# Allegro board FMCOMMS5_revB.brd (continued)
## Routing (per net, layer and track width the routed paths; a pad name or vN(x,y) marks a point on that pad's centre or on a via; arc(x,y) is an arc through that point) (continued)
TX_D5_N_B: length 84.6
  TOP w0.203: P402.H20 v1(78.73,33.28)
  L6_SIG w0.097: v2(26.63,26.71) 26.4,26.95 26.4,27.41 26.15,27.66 26.15,28.03 26.4,28.27 26.4,28.55 26.16,28.78 26.16,29.17 26.4,29.4 26.4,29.68 26.12,29.96 26.12,30.21 26.4,30.49 26.4,30.81 26.09,31.11 26.09,31.37 26.4,31.68 26.4,38.81 30.01,42.41 46.15,42.41 46.28,42.29 46.28,40.48 46.55,40.2 48.67,40.2 48.95,40.48 48.95,42.42 49.08,42.55 50.2,42.55 50.33,42.42 50.33,38.56 50.61,38.28 52.18,38.28 52.46,38.56 52.46,40.3 52.68,40.52 72.97,40.52 73.17,40.32 73.17,38.83 77.57,34.43 79.1,34.43 79.53,34 79.53,33.17 79.4,33.04 78.87,33.04 78.73,33.18 v1(78.73,33.28)
  BOTTOM w0.203: U201.F8 v2(26.63,26.71)
TX_D5_P_A: length 84.5
  TOP w0.203: P401.H19 v1(80,103.24)
  L6_SIG w0.097: v1(80,103.24) 79.77,103.47 79.77,104.06 79.19,104.64 74.77,104.64 74.23,105.18 74.23,107.98 73.8,108.42 72.47,108.42 72.35,108.54 72.35,110.36 72.07,110.64 70.34,110.64 70.06,110.36 70.06,108.55 69.86,108.34 68.05,108.34 67.96,108.44 67.96,110.42 67.71,110.66 65.56,110.66 65.32,110.42 65.32,108.44 65.22,108.34 63.29,108.34 63.19,108.44 63.19,110.42 62.95,110.66 60.8,110.66 60.55,110.42 60.55,108.44 60.46,108.34 58.52,108.34 58.43,108.44 58.43,110.42 58.18,110.66 56.03,110.66 55.79,110.42 55.79,108.44 55.69,108.34 53.76,108.34 53.66,108.44 53.66,110.32 53.38,110.6 51.3,110.6 51.02,110.32 51.02,108.44 50.93,108.34 48.99,108.34 48.9,108.44 48.9,110.42 48.65,110.66 44.27,110.66 42.65,112.28 31.56,112.28 31.16,112.69 30.65,112.69 30.55,112.59 30.3,112.59 30.2,112.69 29.73,112.69 29.64,112.6 29.16,112.6 29.07,112.69 28.59,112.69 28.5,112.6 28.03,112.6 27.94,112.69 27.46,112.69 27.37,112.6 26.9,112.6 26.81,112.69 26.33,112.69 26,112.36 v2(25.34,112.36)
  BOTTOM w0.203: U101.E7 v2(25.34,112.36)
TX_D5_P_B: length 84.6
  TOP w0.203: P402.H19 v1(80,33.28)
  L6_SIG w0.097: v2(26.07,26.15) 26.07,26.81 25.74,27.14 25.74,27.62 25.83,27.71 25.83,28.18 25.74,28.27 25.74,28.75 25.83,28.84 25.83,29.32 25.74,29.4 25.74,29.88 25.83,29.97 25.83,30.45 25.74,30.54 25.74,31.01 25.84,31.11 25.84,31.37 25.74,31.46 25.74,31.97 26.15,32.38 26.15,38.91 29.9,42.67 46.26,42.67 46.53,42.39 46.53,40.58 46.66,40.46 48.57,40.46 48.69,40.58 48.69,42.53 48.97,42.8 50.31,42.8 50.58,42.53 50.58,38.66 50.71,38.53 52.08,38.53 52.2,38.66 52.2,40.4 52.58,40.77 73.08,40.77 73.42,40.43 73.42,38.94 77.67,34.68 79.2,34.68 79.78,34.1 79.78,33.5 v1(80,33.28)
  BOTTOM w0.203: U201.E7 v2(26.07,26.15)
TX_EXT_LO_A: length 47.3
  TOP w0.394: C337.2 34.41,73.8 arc(34.41,74) 34.39,74.19 arc(34.11,75.11) 33.55,75.9 29.71,79.74 18.49,90.96 arc(17.41,92.48) 16.91,94.28 16.91,100.35 arc(17.13,101.49) 17.78,102.45 arc(18.3,102.8) 18.92,102.93 22.57,102.93 arc(23.76,103.16) 24.76,103.83 25.53,104.61 arc(25.76,104.95) v3(25.84,105.35)
  BOTTOM w0.254: v3(25.84,105.35) 25.84,105.5 25.34,106 U101.A12
TX_EXT_LO_B: length 47.2
  TOP w0.394: C339.2 34.59,66.15 arc(34.37,65.02) 33.72,64.05 29.89,60.22 arc(28.3,57.85) 27.75,55.05 27.75,43.51 arc(28.2,41.21) 29.51,39.26 32.02,36.75 arc(33.76,34.13) 34.38,31.05 34.38,30.06 arc(34.12,28.78) 33.4,27.7 31.15,25.44 v2(31.15,25.44)
  BOTTOM w0.254: v2(31.15,25.44) 31.16,25.45 U201.A12
TX_FRAME_N_A: length 84.5
  TOP w0.203: P401.D15 v1(83.81,96.89)
  L6_SIG w0.097: v2(28.16,112.93) 28.4,113.17 28.87,113.17 29.16,113.46 29.43,113.46 29.72,113.17 30,113.17 30.28,113.44 30.58,113.44 30.86,113.17 31.13,113.17 31.44,113.48 31.68,113.48 31.71,113.45 31.99,113.17 32.26,113.17 32.66,113.57 36.54,113.57 37.26,112.85 42.81,112.85 43.87,111.8 46.18,111.8 46.46,112.07 46.46,113.02 46.58,113.14 48.46,113.14 48.59,113.02 48.59,111.62 48.86,111.34 50.95,111.34 51.22,111.62 51.22,112.97 51.35,113.09 53.22,113.09 53.35,112.97 53.35,111.28 53.63,111.01 55.71,111.01 55.99,111.28 55.99,112.66 56.11,112.79 57.99,112.79 58.12,112.66 58.12,111.38 58.39,111.1 60.48,111.1 60.75,111.38 60.75,112.7 60.88,112.83 62.75,112.83 62.88,112.7 62.88,111.5 63.16,111.23 72.79,111.23 75.5,108.52 75.5,105.93 75.77,105.65 79.86,105.65 80.32,105.19 80.32,103.77 80.96,103.14 84.21,103.14 84.6,102.75 84.6,96.72 84.46,96.59 83.95,96.59 83.81,96.73 v1(83.81,96.89)
  BOTTOM w0.203: U101.H9 v2(28.16,112.93)
TX_FRAME_N_B: length 86.2
  TOP w0.203: P402.D15 v1(83.81,26.93)
  L6_SIG w0.097: v2(25.5,28.97) 25.28,28.97 25.14,29.12 25.14,29.26 25.27,29.39 25.27,29.68 24.97,29.98 24.97,30.24 25.27,30.54 25.27,30.81 24.99,31.09 24.99,31.39 25.27,31.67 25.27,31.94 24.95,32.25 24.95,32.63 24.86,32.72 24.86,36.57 25.76,37.46 25.76,39.53 29.59,43.35 36.65,43.35 36.74,43.44 50.55,43.44 52.42,41.58 72.86,41.58 77.42,37.02 78.5,37.02 81.12,34.4 83.66,34.4 84.61,33.45 84.61,26.56 84.48,26.43 83.94,26.43 83.81,26.56 v1(83.81,26.93)
  BOTTOM w0.203: U201.H9 v2(25.5,28.97)
TX_FRAME_P_A: length 84.5
  TOP w0.203: P401.D14 v1(85.08,96.89)
  L6_SIG w0.097: v1(85.08,96.89) 84.85,97.11 84.85,102.85 84.31,103.39 81.06,103.39 80.58,103.88 80.58,105.3 79.97,105.91 75.88,105.91 75.75,106.03 75.75,108.63 72.9,111.48 63.26,111.48 63.13,111.61 63.13,112.81 62.86,113.08 60.77,113.08 60.5,112.81 60.5,111.49 60.37,111.36 58.5,111.36 58.37,111.49 58.37,112.77 58.09,113.04 56.01,113.04 55.73,112.77 55.73,111.39 55.61,111.26 53.73,111.26 53.6,111.39 53.6,113.07 53.33,113.35 51.24,113.35 50.97,113.07 50.97,111.72 50.84,111.59 48.97,111.59 48.84,111.72 48.84,113.12 48.56,113.4 46.48,113.4 46.2,113.12 46.2,112.18 46.08,112.05 43.97,112.05 42.92,113.1 37.36,113.1 36.65,113.82 31.78,113.82 31.69,113.73 31.42,113.73 31.33,113.82 30.52,113.82 30.43,113.74 30.08,113.74 30,113.82 29.52,113.82 29.43,113.73 28.95,113.73 28.87,113.82 28.52,113.82 27.63,112.93 v2(27.03,112.93)
  BOTTOM w0.203: U101.G9 v2(27.03,112.93)
TX_FRAME_P_B: length 86.2
  TOP w0.203: P402.D14 v1(85.08,26.93)
  L6_SIG w0.097: v2(25.5,27.84) 25.5,28.32 24.61,29.21 24.61,29.68 24.7,29.77 24.7,30.24 24.61,30.33 24.61,30.81 24.7,30.89 24.7,31.24 24.61,31.33 24.61,32.14 24.7,32.23 24.7,32.51 24.61,32.59 24.61,36.67 25.51,37.57 25.51,39.63 29.41,43.53 29.41,43.53 29.48,43.61 36.54,43.61 36.63,43.7 50.66,43.7 52.53,41.83 72.97,41.83 77.53,37.27 78.61,37.27 81.23,34.65 83.77,34.65 84.87,33.56 84.87,27.15 v1(85.08,26.93)
  BOTTOM w0.203: U201.G9 v2(25.5,27.84)
TX_MON1_A: length 36.4
  TOP w0.394: C101.2 41.45,128.66 arc(39.94,128.35) 38.65,127.49 35.75,124.6 arc(35.32,124.26) 34.83,124.04 arc(33.63,123.5) 32.59,122.69 28.53,118.63 arc(28.25,118.2) 28.14,117.7 v2(28.14,117.6)
  BOTTOM w0.254: v2(28.14,117.6) U101.M5
TX_MON1_B: length 27.2
  TOP w0.394: C201.2 8.17,21.6 arc(9.02,25.86) 11.44,29.48 13.16,31.2 arc(15.54,32.19) 17.91,31.2 19.69,29.43 arc(20.21,29.08) v2(20.83,28.96)
  BOTTOM w0.254: v2(20.83,28.96) U201.M5
TX_MON2_A: length 20.8
  TOP w0.394: C102.2 8.21,119.03 arc(10.62,113.23) 16.42,110.83 v2(20.98,110.83)
  BOTTOM w0.254: v2(20.98,110.83) U101.A5
TX_MON2_B: length 36.8
  TOP w0.394: C202.2 44.23,13.04 arc(36.32,14.75) 29.82,19.57 v2(27.6,21.79)
  BOTTOM w0.254: v2(27.6,21.79) U201.A5
TX_VCO_1P1V_SUPPLY_A: length 3.9
  TOP w0.394: C104.2 24.93,106.46 24.93,106.95 R123.1 25.34,107.36 v2(25.34,107.84) v2(25.9,108.4)
  BOTTOM w0.254: v2(25.34,107.84) U101.A11 ; U101.B11 v2(25.9,108.4)
TX_VCO_1P1V_SUPPLY_B: length 4.6
  TOP w0.305: v2(30.03,26.71) v2(30.59,26.15) 30.73,26.28 30.73,26.89 31.21,27.37 C204.2 R223.1
  BOTTOM w0.254: v2(30.59,26.15) U201.A11 ; v2(30.03,26.71) U201.B11
TXNRX_A: length 90.5
  TOP w0.394: 80.63,102.6 v1(81.8,102.6)
  L5_SIG w0.124: v1(81.8,102.6) 82.2,102.6 82.33,102.73 82.33,103.03 82.45,103.16 83.87,103.16 83.99,103.29 83.99,103.72 84.12,103.84 84.88,103.84 85.01,103.72 85.01,102.91 85.13,102.78 86.01,102.78 86.14,102.66 86.14,102.02 86.01,101.9 84.78,101.9 84.65,101.77 84.65,101.14 84.78,101.01 86.14,101.01 86.27,100.88 86.27,100.25 86.14,100.12 85.07,100.12 85.07,100.12 83.96,100.12 83.84,100.25 83.84,101.77 83.71,101.89 80.73,101.89 80.6,102.02 80.6,102.52 80.47,102.64 79.33,102.64 79.2,102.77 79.2,103.81 78.91,104.1 77.55,104.1 77.13,104.53 77.13,107.54 77.01,107.67 74.5,107.67 74.37,107.8 74.37,109.4 74.24,109.52 52.72,109.52 47.25,115 45.12,115 44.05,116.07 44.05,117.87 P101.2 41.84,120.09 38.72,120.09 38.57,119.94 29.19,119.94 29.12,120.01 27.98,120.01 24.99,117.03 24.99,116.55 v2(24.77,116.32)
  BOTTOM w0.254: U101.H4 v2(24.77,116.32)
TXNRX_B: length 89.4
  TOP w0.394: 80.63,32.65 v1(81.8,32.65)
  L5_SIG w0.124: v2(22.11,25.58) 22.11,25.58 21.89,25.81 21.4,25.81 19.16,28.05 19.16,35.42 23.58,39.84 25.48,39.84 28.07,42.43 31.58,42.43 34.45,45.3 38.06,45.3 42.03,49.27 P201.2 44.28,47.95 44.28,46.1 50.68,39.7 74.17,39.7 78.07,35.79 78.33,35.79 81.48,32.65 v1(81.8,32.65)
  BOTTOM w0.254: U201.H4 v2(22.11,25.58)
UNNAMED_2_AD9361_I22_RBIAS: length 2.6
  BOTTOM w0.178: 26.47,118.02 27.19,118.74 27.19,118.86 R125.1
  BOTTOM w0.254: 26.47,118.02 U101.L4
UNNAMED_2_AD9361_I22_RXVCOLDOOU: length 3.6
  TOP w0.305: R124.1 22.4,116.92
  TOP w0.356: 22.4,116.92 22.51,116.81 v2(22.51,116.32)
  TOP w0.394: v2(22.51,116.32) v2(23.07,115.76)
  BOTTOM w0.254: U101.G3 v2(23.07,115.76) ; U101.G2 v2(22.51,116.32)
UNNAMED_2_AD9361_I22_XTALN: length 2.7
  BOTTOM w0.254: 31.56,113.49 31.66,113.49 32.31,112.84 C166.2 C165.2
UNNAMED_2_ADL5320_I366_RFIN: length 4.4
  BOTTOM w0.394: U104.1 47.27,125.59 C156.2 ; C156.2 45.51,125.58 FL102.2 44.23,125.59 C156.2
UNNAMED_2_ADL5320_I366_RFOUT: length 5.5
  BOTTOM w0.394: C139.2 53.34,125.96 53.35,125.96 L110.1 C155.2 U104.3
UNNAMED_2_ADL5320_I367_RFIN: length 3.1
  BOTTOM w0.394: FL103.2 11.3,96.75 C114.2 11.31,96.74 U105.1
UNNAMED_2_ADL5320_I367_RFOUT: length 5.5
  BOTTOM w0.394: U105.3 C115.2 L111.1 13.75,88.89 C162.2
UNNAMED_2_ADL5521PRELIM_I290__1: length 3.9
  BOTTOM w0.305: U102.7 15.83,127.27
  BOTTOM w0.394: FL100.4 17.53,125.75 arc(17.25,125.93) 16.92,126 arc(16.15,126.32) 15.83,127.09 15.83,127.27
UNNAMED_2_ADL5521PRELIM_I290_RF: length 1.5
  BOTTOM w0.305: 15.83,131.2 U102.2
  BOTTOM w0.394: 15.83,131.2 15.83,131.64 15.84,131.65 L106.2
UNNAMED_2_ADL5521PRELIM_I290_VB: length 3
  BOTTOM w0.305: 14.94,130.57 U102.1
  BOTTOM w0.394: 14.94,130.57 14.55,130.57 14.28,130.31 14.28,129.68 13.75,129.14 R108.1
UNNAMED_2_ADL5521PRELIM_I290_VP: length 5
  BOTTOM w0.305: U102.8 14.96,127.87
  BOTTOM w0.394: 14.96,127.87 R108.2 C147.2 R109.1
UNNAMED_2_ADL5521PRELIM_I304__1: length 4.5
  BOTTOM w0.305: 11.79,123.13 U103.7
  BOTTOM w0.394: 11.79,123.13 14.65,123.13 arc(14.9,123.08) 15.11,122.94 FL101.4
UNNAMED_2_ADL5521PRELIM_I304_RF: length 1.5
  BOTTOM w0.305: 7.81,123.14 7.82,123.13 U103.2
  BOTTOM w0.394: L108.2 7.81,123.14
UNNAMED_2_ADL5521PRELIM_I304_VB: length 3
  BOTTOM w0.305: 8.41,122.24 U103.1
  BOTTOM w0.394: R110.1 9.84,121.04 9.3,121.58 8.68,121.58 8.41,121.84 8.41,122.24
UNNAMED_2_ADL5521PRELIM_I304_VP: length 5
  BOTTOM w0.305: 11.11,122.24 U103.8
  BOTTOM w0.394: R112.1 C149.2 R110.2 11.11,122.24
UNNAMED_2_CAP_I19_N1: length 1.1
  TOP w0.394: R124.2 22.12,118.06 21.71,118.47 21.71,118.52 C117.1
UNNAMED_2_CAP_I51_N1: length 1.1
  TOP w0.394: R123.2 C105.1
UNNAMED_2_CAP_I135_N1: length 2.1
  BOTTOM w0.203: T106.6 30.08,124.08 28.99,124.08 C106.1
UNNAMED_2_CAP_I136_N1: length 2.1
  BOTTOM w0.203: C107.1 28.2,124.69 28.2,125.79 T106.4
UNNAMED_2_CAP_I137_N1: length 2.1
  BOTTOM w0.203: T105.6 13,110.59 14.09,110.59 C108.1
UNNAMED_2_CAP_I138_N1: length 2.1
  BOTTOM w0.203: T105.4 14.93,108.92 14.93,110.02 C109.1
UNNAMED_2_CAP_I199_N1: length 0.9
  TOP w0.394: C102.1 R122.2
UNNAMED_2_CAP_I200_N1: length 0.9
  TOP w0.394: C101.1 R121.2
UNNAMED_2_CAP_I209_N2: length 2.1
  BOTTOM w0.203: C122.2 33.63,119.98 34.72,119.98 T107.6
UNNAMED_2_CAP_I210_N2: length 2.1
  BOTTOM w0.203: T107.4 32.9,121.74 32.9,120.65 C123.2
UNNAMED_2_CAP_I220_N2: length 2.1
  BOTTOM w0.203: C124.2 18.18,105.88 17.08,105.88 T108.6
UNNAMED_2_CAP_I221_N2: length 2.1
  BOTTOM w0.203: T108.4 18.91,104.11 18.91,105.21 C125.2
UNNAMED_2_CAP_I230_N1: length 1.2
  BOTTOM w0.203: C128.1 21.79,120.9 arc(21.49,121.35) T101.3
UNNAMED_2_CAP_I231_N1: length 1.2
  BOTTOM w0.203: C129.1 21.11,120.21 arc(20.65,120.52) T101.4
UNNAMED_2_CAP_I232_N1: length 1.2
  BOTTOM w0.203: C130.1 19.18,118.28 arc(18.87,118.74) T102.3
UNNAMED_2_CAP_I233_N1: length 1.2
  BOTTOM w0.203: C131.1 18.5,117.6 arc(18.04,117.91) T102.4
UNNAMED_2_CAP_I260_N1: length 2
  TOP w0.203: C126.1 18.62,122.82 arc(18.44,123.74) T103.4
UNNAMED_2_CAP_I261_N1: length 2
  TOP w0.203: C127.1 17.82,122.02 arc(16.9,122.2) T103.6
UNNAMED_2_CAP_I271_N1: length 2.4
  BOTTOM w0.394: T108.3 14.98,100.19 arc(14.7,100) C140.1
UNNAMED_2_CAP_I271_N2: length 9.8
  BOTTOM w0.394: C111.1 C110.2
UNNAMED_2_CAP_I273_N1: length 8.2
  BOTTOM w0.394: T107.3 38.65,127.49 arc(39.94,128.35) 41.45,128.66 C136.1
UNNAMED_2_CAP_I273_N2: length 9.8
  BOTTOM w0.394: C137.1 C136.2
UNNAMED_2_CAP_I281_N2: length 2.1
  TOP w0.356: P101.16 60.45,119.25 C142.2
UNNAMED_2_CAP_I341_N2: length 2
  TOP w0.203: C132.2 34.74,119.73 arc(34.92,120.64) T104.6
UNNAMED_2_CAP_I342_N2: length 2
  TOP w0.203: C133.2 35.54,118.92 arc(36.46,119.11) T104.4
UNNAMED_2_CAP_I345_N2: length 2.5
  BOTTOM w0.394: C138.2 42.31,128.04 FL102.4
UNNAMED_2_CAP_I348_N2: length 2.5
  BOTTOM w0.394: FL103.4 13.75,99.94 C140.2
UNNAMED_2_CNBNC5P_I182_CNTR: length 16.5
  TOP w0.394: J101.1 71.12,133.35 arc(69.75,130.03) 66.43,128.66 R101.2 R121.1
UNNAMED_2_CNBNC5P_I183_CNTR: length 10.9
  TOP w0.394: R122.1 R102.2 8.21,128.43 arc(7.78,130.61) 6.55,132.45 J102.1
UNNAMED_2_FLTRBP4PV2_I360_OUT: length 1.5
  BOTTOM w0.394: T101.1 FL100.2
UNNAMED_2_FLTRBP4PV2_I361_OUT: length 1.5
  BOTTOM w0.394: T102.1 FL101.2
UNNAMED_3_CN160PCDGH_I39_N30: length 1.3
  TOP w0.394: 84.44,116.57 84.39,116.62 84.39,117.79 84.44,117.84
UNNAMED_3_CN160PCDGH_I54_N35: length 2.3
  TOP w0.508: 79.36,122.92 v1(78.2,122.92)
  BOTTOM w0.305: R404.1 78.19,122.93 v1(78.2,122.92)
UNNAMED_3_CN160PCDGH_I216_N30: length 1.3
  TOP w0.394: 84.44,47.89 84.44,46.62
UNNAMED_4_ADM7150_I1046_BYP: length 1.6
  TOP w0.394: U502.3 58.13,56.1 C538.2
UNNAMED_4_ADM7150_I1046_VIN: length 6.6
  TOP w0.394: 60.66,62.98 C535.2 C536.2
  TOP w0.508: 61.7,63 61.7,65.72 61.18,66.25 C644.2
UNNAMED_4_ADM7150_I1142_BYP: length 2.9
  TOP w0.394: U508.3 69.81,72 70.14,72.33 70.14,73.11 C643.2
UNNAMED_4_ADP237X_I1045_FB: length 3.9
  TOP w0.305: 67.33,63.48 U501.5
  TOP w0.394: 67.33,63.48 67.32,63.49 R502.1 R501.2
UNNAMED_4_ADP237X_I1045_SW: length 5.8
  TOP w0.305: U501.7 68.69,61.92
  TOP w0.394: 68.69,61.92 70.97,59.63 L502.1
UNNAMED_4_ADP1755_I730_ADJ: length 2.8
  TOP w0.394: R509.2 R508.1 49.18,82.08 49.47,81.8 U504.9
UNNAMED_4_ADP1755_I730_SS: length 1.5
  TOP w0.305: U504.7 C561.1
UNNAMED_4_ADP1755_I730_VOUT1: length 6
  TOP w0.305: 49.21,80.89 49.47,81.15 U504.10 ; 50.39,78.92 U504.13 U504.14 ; U504.12 49.25,79.85 ; U504.11 49.25,80.5
  TOP w0.394: C566.1 47.68,77.72 ; C565.1 45.85,77.72 ; C567.1 48.62,77.72 ; R508.2 48.62,81.03 ; C564.1 46.77,77.72
UNNAMED_4_ADP1755_I776_ADJ: length 2.8
  TOP w0.394: R513.2 R512.1 49.17,75.26 49.46,74.98 U505.9
UNNAMED_4_ADP1755_I776_SS: length 1.5
  TOP w0.305: U505.7 C577.1
UNNAMED_4_ADP1755_I776_VOUT1: length 5.9
  TOP w0.305: U505.11 49.24,73.68 ; U505.12 49.24,73.03 ; 49.2,74.07 49.46,74.33 U505.10 ; U505.14 U505.13 50.38,72.1
  TOP w0.394: C580.1 46.76,70.9 ; C582.1 47.67,70.9 ; R512.2 48.61,74.31 ; C583.1 45.84,70.9 ; C581.1 48.61,70.9
UNNAMED_4_ADP1755_I987_ADJ: length 2.8
  TOP w0.394: R517.2 R516.1 49.2,61.67 49.48,61.39 U506.9
UNNAMED_4_ADP1755_I987_SS: length 1.5
  TOP w0.305: C595.1 51.72,63.81 U506.7
UNNAMED_4_ADP1755_I987_VOUT1: length 5.9
  TOP w0.305: 49.22,60.48 49.48,60.74 U506.10 ; U506.11 49.26,60.09 ; U506.12 49.26,59.44 ; 50.41,58.51 U506.13 U506.14
  TOP w0.394: C598.1 48.64,57.31 ; R516.2 48.64,60.71 ; C514.1 46.78,57.31 ; C650.1 45.87,57.31 ; C599.1 47.7,57.31
UNNAMED_4_ADP1755_I997_ADJ: length 2.8
  TOP w0.394: R521.1 R520.1 49.21,68.48 49.5,68.19 U507.9
UNNAMED_4_ADP1755_I997_SS: length 1.5
  TOP w0.305: C621.1 51.72,69.93 51.74,69.91 U507.7
UNNAMED_4_ADP1755_I997_VOUT1: length 6
  TOP w0.305: U507.11 49.28,66.89 ; 49.24,67.28 49.5,67.54 U507.10 ; U507.12 49.28,66.24 ; U507.14 U507.13 50.42,65.32
  TOP w0.394: C626.1 46.8,64.11 ; C627.1 45.89,64.11 ; R520.2 48.65,67.4 ; C624.1 47.71,64.11 ; C625.1 48.65,64.11
UNNAMED_4_ADP2164_I831_FB: length 3
  TOP w0.305: U503.4 65.61,86.33 65.57,86.37
  TOP w0.394: R506.1 R505.2 65.34,86.6 65.57,86.37
UNNAMED_4_ADP2164_I831_PVIN1: length 9.4
  TOP w0.305: U503.13 70.4,82.55 v1(70.49,82.64)
  TOP w0.394: C505.1 71.03,83.55 ; R504.2 71.41,85.71 ; R523.2 71.03,84.52 ; C504.1 71.03,82.56 ; U503.12 68.84,81.55
  BOTTOM w0.394: E504.2 64.53,68 E503.1 64.51,70.17 64.51,71.29 ; 65.51,73.83 65.17,73.48 E501.1
  vias: v1(68.61,80.99) v1(69.4,80.99)
UNNAMED_4_ADP2164_I831_SW1: length 7.3
  TOP w0.305: 67.17,80.51 66.45,80.51 ; 67.17,80.51 67.34,80.51 67.66,80.19 L503.1 ; 67.17,80.51 66.91,80.76 U503.11 ; 66.45,80.51 66.26,80.7 U503.10 ; 66.45,80.51 65.9,80.51 65.61,80.79 U503.9
UNNAMED_4_ADP2164_I831_SYNC: length 4.6
  TOP w0.305: v3(68.54,85.38) 68.42,85.5 U503.1 ; U503.3 66.26,86.37 v3(66.25,86.37) ; U503.14 69.37,83.2 v3(69.4,83.17)
  TOP w0.394: v3(66.25,86.37) 66.45,86.57 C549.1 ; v3(72.85,84.85) 72.52,84.52 R523.1
UNNAMED_4_CAP_I833_N2: length 1.3
  TOP w0.394: C552.1 62.24,78.89 ; C551.1 63.43,78.76
UNNAMED_4_FERRITE_I816_N2: length 4.2
  BOTTOM w0.394: E514.1 E512.1 51.72,72.35 E515.2 E513.2 E1.1
UNNAMED_5_AD7291_I69_DCAP: length 1.8
  TOP w0.254: C313.1 40.33,47.75 40.09,47.51 U304.8
UNNAMED_5_AD7291_I69_VIN0: length 5
  TOP w0.305: U304.18 34.83,47.51 34.82,47.5 34.21,47.5 v3(34.1,47.62)
  L5_SIG w0.124: v3(35.06,49.44) 35.06,48.58 v3(34.1,47.62)
  BOTTOM w0.394: v3(35.06,49.44) 35.28,49.44 35.74,49.9 R305.2 35.74,50.94 R308.2
UNNAMED_5_AD7291_I69_VIN1: length 7.2
  TOP w0.254: U304.19 34.2,47.01 v3(34.07,46.88)
  BOTTOM w0.394: R307.2 R304.2 37.64,49.15 35.36,46.88 v3(34.07,46.88)
UNNAMED_5_AD7291_I69_VIN2: length 11.2
  TOP w0.305: v3(34.12,46.22) 34.15,46.22 34.44,46.51 U304.20
  BOTTOM w0.394: v3(34.12,46.22) 35.16,46.22 35.69,45.68 38.3,45.68 39.26,46.64 39.26,48.44 39.7,48.89 R303.2 R306.2
UNNAMED_5_AD7291_I69_VIN3: length 4.3
  TOP w0.254: U304.1 35.94,44.89 35.77,44.72 34.73,44.72 v3(34.2,44.18)
  BOTTOM w0.394: v3(34.2,44.18) R309.2 R312.2
UNNAMED_5_AD7291_I69_VIN4: length 3.3
  TOP w0.254: U304.2 36.44,44.58 v3(36.1,44.23)
  BOTTOM w0.394: v3(36.1,44.23) 36.31,44.03 R310.2 36.31,42.82 36.31,42.82 36.31,42.48 R313.2
UNNAMED_5_AD7291_I69_VIN5: length 3.3
  TOP w0.254: U304.3 36.94,44.25 v3(36.99,44.21)
  BOTTOM w0.394: R314.2 R327.2 37.51,43.69 v3(36.99,44.21)
UNNAMED_5_AD7291_I69_VIN6: length 4.2
  TOP w0.254: U304.4 37.44,44.64 37.93,44.16 v3(38.67,44.16)
  BOTTOM w0.394: R328.2 R326.2 39.28,43.55 v3(38.67,44.16)
UNNAMED_5_AD7291_I69_VIN7: length 6.6
  TOP w0.254: U304.5 37.94,44.91 38.23,44.62 39.15,44.62 39.71,44.06 41.64,44.06 v3(41.79,44.21)
  BOTTOM w0.394: v3(41.79,44.21) 41.66,44.08 R325.2 R329.2
UNNAMED_5_AD7291_I69_VREF: length 1.9
  TOP w0.254: U304.7 39.94,47.01 40.4,46.55 C314.1
UNNAMED_5_ADCLK846_I21_CLK: length 3.9
  TOP w0.305: 11.69,69.74 U301.3
  TOP w0.394: 11.69,69.74 11.45,69.5 10.04,69.5 ; C301.2 10.04,69.5 ; 10.04,69.5 R360.1
UNNAMED_5_ADCLK846_I21_CLKN: length 2.4
  TOP w0.305: U301.2 12.56,70.24 12.38,70.42
  TOP w0.394: C302.1 11.94,70.86 12.38,70.42
UNNAMED_5_ADCLK846_I21_OUT2: length 3
  TOP w0.203: U301.18 18.05,70.74 18.12,70.67 18.63,70.67 18.78,70.83 19.77,70.83 C318.1
UNNAMED_5_ADCLK846_I21_OUT2N: length 3
  TOP w0.203: U301.17 18.05,70.24 18.12,70.31 18.77,70.31 18.93,70.47 19.77,70.47 C319.1
UNNAMED_5_ADF5355_I6_CPOUT: length 4.6
  TOP w0.305: U302.7 26.45,67.32 26.63,67.15 C328.2
  TOP w0.394: R316.2 28.61,66.15 28.61,66.16 C329.2 C328.2
UNNAMED_5_ADF5355_I6_CREG1: length 2.1
  TOP w0.305: U302.25 22.21,72.4 21.95,72.66 21.67,72.66 21.3,73.03 C327.2
UNNAMED_5_ADF5355_I6_CREG2: length 2.4
  TOP w0.305: U302.32 22.25,68.9 21.5,68.16
  TOP w0.394: 21.5,68.16 21.31,67.97 C326.2
UNNAMED_5_ADF5355_I6_RFOUTB: length 4
  TOP w0.305: R335.2 29.94,72.32 29.01,71.4 U302.14
  TOP w0.394: R335.2 C353.2
UNNAMED_5_ADF5355_I6_RSET: length 2.5
  TOP w0.305: U302.22 24.45,73.6 25.48,74.64 R323.2
UNNAMED_5_ADF5355_I6_VBIAS: length 3.9
  TOP w0.305: U302.24 23.45,73.68 23.2,73.93 22.18,73.93 21.96,74.15 C322.2 21.96,75.8 C325.2
UNNAMED_5_ADF5355_I6_VREF: length 2.8
  TOP w0.305: C324.2 24.06,74.77 C321.2 24.07,74.03 23.95,73.92 U302.23
UNNAMED_5_ADF5355_I6_VTUNE: length 15.1
  TOP w0.305: U302.20 v3(25.45,73.9)
  TOP w0.394: v3(31.25,64.81) 31.18,64.88 C330.2 30.46,64.88 R316.1
  BOTTOM w0.394: v3(31.25,64.81) 31.18,64.88 30.93,64.88 27.64,68.16 27.64,72.4 26.15,73.9 v3(25.45,73.9)
UNNAMED_5_ADG91X_I150_RF1: length 1.6
  BOTTOM w0.305: C351.1 U306.8
UNNAMED_5_ADG91X_I150_RF2: length 1.6
  BOTTOM w0.305: U306.5 18.99,65.16 18.98,65.17 18.98,65.72 18.98,65.73 C352.1
UNNAMED_5_ADG91X_I150_RFC: length 27.2
  L6_SIG w0.124: v3(21.02,82.52) 22.83,80.71 22.83,66.27 21.81,65.25 20.55,65.25 18.71,63.41 18.71,61.11 v3(18.88,60.95)
  BOTTOM w0.305: v3(18.88,60.95) 18.99,60.84 U306.4 ; U305.4 21.01,82.51 v3(21.02,82.52)
UNNAMED_5_ADG91X_I151_RF1: length 1.8
  BOTTOM w0.305: U305.8 19.06,75 C349.2
UNNAMED_5_ADG91X_I151_RF2: length 1.8
  BOTTOM w0.305: U305.5 C350.2
UNNAMED_5_CAP_I5_N1: length 7.6
  TOP w0.394: C301.1 R301.2 J301.1
UNNAMED_5_CAP_I98_N1: length 1.6
  TOP w0.394: R315.2 27.21,64.17 27.62,64.58 C329.1
UNNAMED_5_CAP_I121_N1: length 1.5
  TOP w0.305: U307.2 35.13,72.56 35.3,72.72 C336.1
UNNAMED_5_CAP_I122_N1: length 1.5
  TOP w0.305: U307.3 34.63,72.5 34.41,72.72 C337.1
UNNAMED_5_CAP_I123_N1: length 1.9
  TOP w0.305: U307.11 35.13,67.77 35.13,67.76 35.13,67.55 35.47,67.21 C338.1
UNNAMED_5_CAP_I124_N1: length 1.7
  TOP w0.305: C339.1 34.59,67.73 34.63,67.76 U307.10
UNNAMED_5_CAP_I187_N2: length 13.7
  TOP w0.394: C390.2 31.88,72.32 C353.1 v1(31.89,73.01)
  L6_SIG w0.124: J302.1 32.4,79.92 32.4,73.57 31.89,73.07 v1(31.89,73.01)
UNNAMED_5_DIOLED_I51_P: length 1.5
  BOTTOM w0.394: R302.1 DS301.A
UNNAMED_5_RES_I192_N2: length 1.8
  TOP w0.394: Y301.3 10.62,71.16 arc(10.59,70.97) 10.49,70.79 10.05,70.35 R360.2
UNNAMED_9_AD9361_I119_RBIAS: length 2.6
  BOTTOM w0.178: R225.1 18.99,28.7 20.41,27.28
  BOTTOM w0.254: 20.41,27.28 U201.L4
UNNAMED_9_AD9361_I119_RXVCOLDOO: length 3.8
  TOP w0.305: v2(22.67,23.88) v2(22.11,23.32) 21.62,23.32 C216.1 21.47,23.17 21.47,22.82 21.15,22.5 R224.1
  BOTTOM w0.254: U201.G3 v2(22.67,23.88) ; U201.G2 v2(22.11,23.32)
UNNAMED_9_AD9361_I119_XTALN: length 2.9
  BOTTOM w0.254: U201.M12 24.94,32.91
  BOTTOM w0.394: 24.94,32.91 24.94,33.95 C266.2 C265.2
UNNAMED_9_ADL5320_I225_RFIN: length 3.1
  BOTTOM w0.394: U204.1 13.29,46.06 C256.2 13.29,44.28 FL202.2
UNNAMED_9_ADL5320_I225_RFOUT: length 5.5
  BOTTOM w0.394: C239.2 10.84,52.13 L210.1 C255.2 U204.3
UNNAMED_9_ADL5320_I226_RFIN: length 3.1
  BOTTOM w0.394: FL203.2 40.88,10.48 C214.2 40.89,10.49 U205.1
UNNAMED_9_ADL5320_I226_RFOUT: length 5
  BOTTOM w0.394: U205.3 C215.2 L211.1 48.71,10.5 C262.2
UNNAMED_9_ADL5521PRELIM_I151__1: length 1.6
  BOTTOM w0.305: 15.85,11.72 U203.7
  BOTTOM w0.394: FL201.4 15.85,12.71 15.85,11.72
UNNAMED_9_ADL5521PRELIM_I151_RF: length 1.5
  BOTTOM w0.305: 15.85,7.77 U203.2
  BOTTOM w0.394: L208.2 15.85,6.92 15.85,7.77
UNNAMED_9_ADL5521PRELIM_I151_VB: length 3
  BOTTOM w0.305: 16.72,8.43 U203.1
  BOTTOM w0.394: R210.1 17.72,9.86 17.22,9.36 17.22,8.72 16.93,8.43 16.72,8.43
UNNAMED_9_ADL5521PRELIM_I151_VP: length 5
  BOTTOM w0.305: 16.82,11.13 U203.8
  BOTTOM w0.394: R212.1 C249.2 R210.2 16.82,11.13
UNNAMED_9_ADL5521PRELIM_I159__1: length 1.6
  BOTTOM w0.305: U202.7 11.92,19.69 11.93,19.7
  BOTTOM w0.394: 11.93,19.7 FL200.4
UNNAMED_9_ADL5521PRELIM_I159_RF: length 1.5
  BOTTOM w0.305: 7.76,19.69 U202.2
  BOTTOM w0.394: L206.2 6.9,19.69 7.76,19.69
UNNAMED_9_ADL5521PRELIM_I159_VB: length 3
  BOTTOM w0.305: 8.41,18.8 U202.1
  BOTTOM w0.394: 8.41,18.8 8.41,18.4 8.68,18.14 9.3,18.14 9.84,17.6 R208.1
UNNAMED_9_ADL5521PRELIM_I159_VP: length 5
  BOTTOM w0.305: 11.11,18.8 U202.8
  BOTTOM w0.394: 11.11,18.8 R208.2 C247.2 R209.1
UNNAMED_9_CAP_I23_N2: length 2.1
  BOTTOM w0.203: T208.4 34.32,19.72 33.22,19.72 C225.2
UNNAMED_9_CAP_I24_N2: length 2.1
  BOTTOM w0.203: T208.6 32.55,17.89 32.55,18.99 C224.2
UNNAMED_9_CAP_I30_N2: length 2.1
  BOTTOM w0.203: C222.2 18.46,34.44 18.46,35.53 T207.6
UNNAMED_9_CAP_I31_N2: length 2.1
  BOTTOM w0.203: 17.99,33.5 17.78,33.71 16.69,33.71 T207.4
UNNAMED_9_CAP_I50_N2: length 2
  TOP w0.203: C233.2 19.51,36.35 arc(19.33,37.27) T204.4
UNNAMED_9_CAP_I51_N2: length 2
  TOP w0.203: C232.2 18.7,35.55 arc(17.79,35.73) T204.6
UNNAMED_9_CAP_I55_N1: length 2
  TOP w0.203: C227.1 16.42,18.63 arc(16.23,17.71) T203.6
UNNAMED_9_CAP_I56_N1: length 2
  TOP w0.203: C226.1 15.61,19.43 arc(14.69,19.25) T203.4
UNNAMED_9_CAP_I69_N1: length 2.1
  BOTTOM w0.203: C207.1 28.59,15.56 29.68,15.56 T206.4
UNNAMED_9_CAP_I70_N1: length 2.1
  BOTTOM w0.203: T206.6 27.8,13.85 27.8,14.95 C206.1
UNNAMED_9_CAP_I71_N1: length 2.1
  BOTTOM w0.203: T205.4 12.64,29.01 13.74,29.01 C209.1
UNNAMED_9_CAP_I72_N1: length 2.1
  BOTTOM w0.203: C208.1 14.36,29.8 14.36,30.89 T205.6
UNNAMED_9_CAP_I92_N1: length 0.9
  TOP w0.394: C202.1 R222.2
UNNAMED_9_CAP_I96_N1: length 0.9
  TOP w0.394: R221.2 C201.1
UNNAMED_9_CAP_I101_N1: length 1.1
  TOP w0.394: C205.1 32.01,29.22 32.01,29.04 R223.2
UNNAMED_9_CAP_I111_N1: length 1.1
  TOP w0.394: 20.37,22.93 20.07,22.62 20.02,22.62 C217.1
UNNAMED_9_CAP_I126_N2: length 2.2
  TOP w0.394: P201.16 60.74,49.28 C242.2
UNNAMED_9_CAP_I165_N1: length 1.2
  BOTTOM w0.203: C231.1 20.83,19.31 arc(20.53,18.85) T202.4
UNNAMED_9_CAP_I167_N1: length 1.2
  BOTTOM w0.203: C230.1 20.15,19.99 arc(19.69,19.69) T202.3
UNNAMED_9_CAP_I168_N1: length 1.2
  BOTTOM w0.203: C229.1 18.22,21.92 arc(17.91,21.47) T201.4
UNNAMED_9_CAP_I170_N1: length 1.2
  BOTTOM w0.203: C228.1 17.53,22.61 arc(17.08,22.3) T201.3
UNNAMED_9_CAP_I178_N1: length 4.1
  BOTTOM w0.394: C210.1 37.69,15.45 arc(37.53,16.28) T208.3
UNNAMED_9_CAP_I178_N2: length 9.8
  BOTTOM w0.394: C211.1 C210.2
UNNAMED_9_CAP_I187_N1: length 6.1
  BOTTOM w0.394: T207.3 13.05,37.35 10.6,39.8 arc(10.32,40.22) 10.22,40.71 C236.1
UNNAMED_9_CAP_I187_N2: length 9.8
  BOTTOM w0.394: C237.1 C236.2
UNNAMED_9_CAP_I208_N2: length 2.5
  BOTTOM w0.394: C238.2 10.84,41.08 FL202.4
UNNAMED_9_CAP_I210_N2: length 2
  BOTTOM w0.394: C240.2 37.68,12.42 FL203.4
UNNAMED_9_CNBNC5P_I87_CNTR: length 17.2
  TOP w0.394: R222.1 R202.2 64.9,13.04 arc(69.28,11.41) 71.12,7.12 J202.1
UNNAMED_9_CNBNC5P_I93_CNTR: length 9
  TOP w0.394: R221.1 R201.2 8.17,9.91 arc(7.85,8.28) 6.92,6.89 5.22,5.19 J201.1
UNNAMED_9_FLTRBP4PV2_I215_OUT: length 1.9
  BOTTOM w0.394: FL200.2 14.63,19.96 arc(14.68,20.26) 14.85,20.51 T201.1
UNNAMED_9_FLTRBP4PV2_I217_OUT: length 4.9
  BOTTOM w0.394: T202.1 16.7,17.13 arc(16.08,16.19) 15.86,15.09 FL201.2
VADJ: length 140.2
  TOP w0.394: P401.G39 79.34,129.3 v1(75.34,129.3) ; v1(76.77,59.55) 79.14,59.55 P402.G39
  L5_SIG w0.124: v1(62.69,76.21) 64.17,74.74 64.17,64.12 68.74,59.55 v1(76.77,59.55)
  L6_SIG w0.124: v1(75.34,129.3) 75.34,128.16 77.15,126.35 80.7,126.35 82.3,124.75 83.68,124.75 84.31,124.12 86.01,124.12 86.62,123.51 87.41,123.51 90.43,120.48 90.43,85.59 88.93,84.09 62.72,84.09 62.14,83.5 62.14,77.56 v1(62.67,77.03)
  BOTTOM w0.394: v1(62.69,76.21) 62.69,77 v1(62.67,77.03) 62.64,77.05 59.37,77.05 55.56,73.24 C619.1 C618.1 ; C618.1 53.17,72.48 E515.1 ; C618.1 53.93,73.24
XTALN_A: length 51
  TOP w0.254: U301.24 14.01,72.1 v3(13.75,72.35)
  BOTTOM w0.394: v3(13.75,72.35) 13.75,74.09 13.08,74.76 13.08,81.12 17.26,85.3 18.55,85.3 23.64,90.4 24.4,90.4 29.02,95.02 29.02,105.34 33.94,110.27 C165.1
XTALN_B: length 51
  TOP w0.254: v3(15.76,72.35) 15.51,72.1 U301.21
  BOTTOM w0.394: v3(15.76,72.35) 15.76,71.77 17.08,70.45 17.08,68.52 15.98,67.42 12.53,67.42 11.21,66.1 11.21,60.04 13.94,57.31 15.21,57.31 18.53,53.99 18.53,50.98 21.95,47.56 23.25,47.56 26.12,44.69 26.12,35.99 C265.1

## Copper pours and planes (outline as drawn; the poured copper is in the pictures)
3.3VAUX on L3_PWR: 90.75,74.55 90.76,74.56 90.76,117.77 90.75,117.78 90.75,118.21 88.78,120.18 85,120.18 84.82,120 84.82,118.2 86.42,116.6 86.42,85.64 86.82,85.23 86.9,85.23 88.2,83.93 88.2,51.88 87.46,51.14 38.34,51.14 36.48,49.29 35.59,49.29 35.29,48.98 33.82,48.98 33.76,48.93 33.76,45.66 34.09,45.33 36.18,45.33 36.81,44.69 36.81,40.83 37.14,40.5 90.63,40.5 90.76,40.63 90.76,41.08 90.75,41.1
5V on TOP: 53.88,55.97 53.88,51.35 53.65,51.12 51.49,51.12 51.39,51.22 51.39,53.45 51.3,53.54 49.16,53.54 49.16,52.62 49.11,52.57 48.5,52.57 48.45,52.62 48.45,53.25 48.47,53.28 48.42,53.33 48.42,55.66 48.85,56.1 53.75,56.1
5V on BOTTOM: 44.85,38.33 51.44,44.92 51.44,56.48 52.18,57.21 57.59,57.21 58.17,56.63 58.17,41.24 51.35,34.42 30.96,34.42 28.02,37.35 28.02,44.08 28.51,44.56 31.48,44.56 32.49,43.55 32.49,41.26 35.43,38.33
12V on TOP: 72.85,67.14 72.85,64.94 73.19,64.6 75.39,64.6 75.52,64.73 75.52,66.54 75.75,66.76 78.27,66.76 78.39,66.64 78.39,63.03 78.32,62.95 73.87,62.95 73.79,63.03 73.79,63.46 73.49,63.77 70.21,63.77 70.04,63.94 70.04,66.18 69.96,66.26 69.86,66.26 69.83,66.28 69.83,66.99 69.98,67.14
12V on L3_PWR: 84.82,126.63 87.89,126.63 88.02,126.5 88.02,121.07 87.74,120.79 84.44,120.79 84.06,120.41 84.06,117.64 85.92,115.77 85.73,115.58 85.73,85.15 87.51,83.38 87.56,83.38 87.56,52.44 87.33,52.21 85.02,52.21 84.74,52.49 84.74,62.32 83.93,63.13 78.34,63.13 78.13,62.92 74.72,62.92 74.38,63.26 74.38,67.09 74.51,67.22 77.93,67.22 77.97,67.26 82.29,67.26 82.89,67.86 82.89,74.28 74.76,82.41 74.68,82.41 74.68,108.75 78.65,112.71 78.65,125.77 78.82,125.95 84.13,125.95
12V on L8_PWR: 84.82,126.63 87.56,126.63 87.56,52.44 87.33,52.21 85.02,52.21 83.8,53.43 83.8,60.67 81.34,63.13 77.66,63.13 77.5,62.98 67.39,62.98 67.14,63.23 67.14,67.68 75.57,67.68 75.59,67.67 78.23,67.67 80.46,69.9 80.46,76.71 78.65,78.52 78.65,125.77 78.82,125.95 84.13,125.95
GND_POWER on TOP: 8.57,0.01 0.01,8.57 0.01,130.42 8.57,138.98 89.4,138.98 89.4,125.48 91.45,125.48 91.45,0.04 91.42,0.01 ; 11 cut-outs
GND_POWER on BOTTOM: 8.57,0.01 0.01,8.57 0.01,130.42 8.57,138.98 89.4,138.98 89.4,125.48 91.45,125.48 91.45,0.04 91.42,0.01 ; 7 cut-outs
GND_POWER on L2_GND, L4_GND, L7_GND, L9_GND: 8.57,0 0,8.57 0,130.42 8.57,139 89.4,139 89.4,125.48 91.45,125.48 91.45,0
GND_POWER on L3_PWR: 12.33,110.17 13.55,111.39 13.55,118.28 13.84,118.57 27.4,118.57 30.89,115.07 30.89,105.09 25.46,99.66 25.38,99.66 25.38,85.2 24.9,84.72 15.48,84.72 15.17,85.03 15.17,102.86 12.33,105.7
GND_POWER on L3_PWR: 27.36,15.91 26.07,17.21 21.85,17.21 18.32,20.74 18.32,28.63 22.23,32.53 40.68,32.53 47.81,39.66 81.97,39.66 82.58,39.05 82.58,21.65 76.84,15.91
GND_POWER on L8_PWR: 24.76,32.49 18.68,26.4 18.68,25.82 24.3,20.19 28.21,20.19 29.8,21.78 35.29,21.78 36.13,20.94 36.13,17.16 36.33,16.95 39.99,16.95 40.01,16.93 70.42,16.93 71.99,18.5 71.99,37.73 65.44,44.28 47,44.28 46.21,43.5 46.21,31.94 44.38,30.11 40.42,30.11 38.04,32.49
GND_POWER on L8_PWR: 25.28,120 25.51,120 31.99,113.53 34.65,113.53 36.2,115.07 36.2,119.49 36.43,119.72 55.81,119.72 56.52,120.43 56.52,130.92 56.88,131.28 68,131.28 68.41,130.87 68.41,115.58 65.21,112.38 65.21,93.54 64.68,93 36.91,93 35.64,94.27 35.64,99.23 27.26,107.61 25.2,107.61 23.4,109.41 22.96,108.97 22.96,108.95 22.21,108.95 18.88,112.28 18.88,113.6
VDD_AMP_5V on BOTTOM: 58.81,53.12 58.81,50.56 58.99,50.38 71.46,50.38 71.48,50.41 75.62,50.41 76.03,50 76.03,37.2 76.21,37.02 89.26,37.02 89.44,37.2 89.44,39.99 89.24,40.2 82.28,40.2 81.92,40.55 81.92,53.35 80.63,54.65 59.16,54.65 58.78,54.27 58.78,53.15
VDD_AMP_5V on L3_PWR: 77.36,15.37 83.85,21.86 83.85,39.84 84.21,40.2 89.26,40.2 89.49,39.97 89.49,17.87 79.81,8.19 27.8,8.19 27.44,8.55 27.44,14.9 27.92,15.38 51.42,15.38 51.43,15.37
VDD_AMP_5V on L8_PWR: 28.68,124.8 11.56,124.8 10.96,124.19 10.96,19.77 16.09,14.64 20.82,14.64 20.92,14.54 20.92,9.32 21.34,8.9 50.22,8.9 50.25,8.93 51.47,8.93 51.77,8.62 51.77,7.02 51.67,6.92 9.4,6.92 6.8,9.53 6.8,129.9 7.7,130.8 55.13,130.8 55.33,130.59 55.33,120.79 55.07,120.54 32.95,120.54
VDD_EXT_LO_3P3 on TOP: 68.11,70.42 68.18,70.35 72.63,70.35 73.01,70.73 73.01,75.73 72.93,75.81 71.76,75.81 71.53,75.58 71.53,73.04 71.38,72.89 70.95,72.89 70.72,72.66 70.72,71.82 70.67,71.82 70.11,71.26 68.16,71.26 68.11,71.21
VDD_EXT_LO_3P3 on L3_PWR: 55.2,71.01 55.2,65.75 55.41,65.54 66.63,65.54 66.66,65.57 71.97,65.57 73.08,66.69 73.08,71.59 68.46,76.21 57.46,76.21 57.39,76.14 23.71,76.14 21.42,73.85 21.42,67.48 21.9,66.99 41.36,66.99 41.61,67.25 41.61,67.49 41.6,67.49 41.6,70.72 42.22,71.34 54.87,71.34
VDD_INTERFACE_A on BOTTOM: 49.97,72.37 49.8,72.2 42.76,72.2 42.48,72.48 42.48,78.74 42.67,78.93 54.61,78.93 54.57,78.89 54.57,76.47 54.12,76.47 52.99,75.34 52.99,75.34 52.26,74.61 50.87,74.61 49.97,73.71
VDD_INTERFACE_A on L3_PWR: 42.26,117.88 42.26,99.24 55.94,85.56 55.94,77.05 55.85,76.96 54.69,76.96 54.68,76.97 23.05,76.97 20.84,74.76 20.84,64.71 20.78,64.66 20.78,51.88 28,44.67 36.18,44.67 36.28,44.56 36.28,41.67 34.37,39.76 34.37,37.73 33.6,36.96 14.14,36.96 13.61,37.49 13.61,82.12 15.22,83.73 28.05,83.73 28.07,83.76 34.83,83.76 37.96,80.63 43.26,80.63 43.85,81.22 43.85,83.48 34.54,92.79 34.54,99.75 36.33,101.54 36.33,128.28 37.65,129.6 68.05,129.6 68.41,129.25 68.41,124.57 67.98,124.14 48.52,124.14
VDD_INTERFACE_B on BOTTOM: 47.13,70.83 48.97,70.83 49.77,70.04 50.21,70.04 50.24,70.07 50.24,70.73 49.97,71 49.97,71.79 49.92,71.84 47.14,71.84 46.95,71.65 46.37,71.65 46.36,71.66 43.23,71.66 43.11,71.54 43.11,69.76 43.22,69.65 46.58,69.65 47.13,70.21
VDD_INTERFACE_B on L3_PWR: 68,64.99 54.8,64.99 54.54,65.24 54.54,70.7 54.44,70.8 42.5,70.8 42.11,70.41 42.11,67.65 42.44,67.32 44.15,67.32 47.23,64.25 47.23,59.25 47.73,58.74 58.05,58.74 58.08,58.78 73.83,58.78 74.58,59.52 74.58,62.19 73.26,63.51 73.26,64.88 72.88,65.27 68.16,65.27 68,65.11
VDD_INTERFACE_B on L8_PWR: 77.5,61.63 79.15,59.98 79.43,59.98 79.51,59.91 82.58,59.91 82.94,59.55 82.94,52.97 84.34,51.57 87.59,51.57 88.12,52.11 88.12,120.31 88.4,120.59 90.79,120.59 90.91,120.46 90.91,47.87 90.38,47.33 82.38,47.33 77.66,52.06 71.48,52.06 70.82,52.72 70.82,61.63
VDD_INTERFACE_B on L8_PWR: 36.43,32.91 36.86,33.34 36.86,52.9 38.69,54.72 52.79,54.72 53.3,55.23 53.3,61 53.27,61.02 53.27,63.26 54.19,64.17 54.19,70.85 54.06,70.98 43.24,70.98 43.07,70.82 43.07,69.56 43.08,69.56 43.37,69.27 43.37,59.4 42.5,58.53 30.92,58.53 28.02,55.64 28.02,39.2 25.26,36.44 25.26,33.01 25.36,32.91
VDD_LNA_3P3 on BOTTOM: 56.45,68.35 61.51,68.35 61.91,68.75 63.23,68.75 63.28,68.7 63.28,67.23 63.24,67.18 56.38,67.18 56.27,67.28 56.27,68.18
VDD_LNA_3P3 on L3_PWR: 12.8,112.67 12.81,112.66 12.81,111.44 11.82,110.45 11.82,105.27 14.66,102.43 14.66,84.59 12.89,82.82 12.89,18.83 17.33,14.39 26.55,14.39 26.78,14.16 26.78,9.31 26.75,9.33 26.75,8.62 26.42,8.29 9.53,8.29 6.84,10.99 6.84,125.84 6.8,125.88 6.8,126.54 6.51,126.83 6.51,128.51 6.81,128.82 12.61,128.82 12.8,128.63
VDD_LNA_3P3 on L8_PWR: 63.63,60.9 69.81,60.9 70.11,60.59 70.11,52.01 70.9,51.22 77.3,51.22 79.48,49.03 79.48,10.02 78.93,9.46 21.67,9.46 21.47,9.66 21.47,14.39 21.67,14.59 36.08,14.59 36.33,14.85 36.33,16.07 36.56,16.29 70.95,16.29 72.93,18.28 72.93,38.01 63.23,47.71 63.23,60.49
VDD_RF_SW on BOTTOM: 52.48,68.59 52.53,68.54 55.81,68.54 56.75,69.48 56.69,69.54 56.69,69.62 57.18,70.11 57.18,70.55 57.1,70.63 53.5,70.63 53.25,70.88 52.53,70.88 52.48,70.83
VDD_VCO_5V on L3_PWR: 41.64,59.63 41.64,55.46 41.77,55.33 43.98,55.33 46.77,58.13 46.77,63.59 43.82,66.54 22.03,66.54 21.65,66.15 21.65,62.5 22.08,62.06 34.86,62.06 37.22,64.43 41.36,64.43 41.94,63.84 41.94,59.93
VDDA_GPO_A on BOTTOM: 60.02,74.41 60.02,73.33 60.22,73.12 63.79,73.12 63.86,73.19 63.86,74.65 63.72,74.78 60.39,74.78
VDDA_GPO_A on L8_PWR: 57.82,82.82 57.82,73.49 58.1,73.22 63.91,73.22 64.19,73.49 64.19,91.3 63.66,91.83 35.64,91.83 34.63,92.85 34.63,98.01 34.6,98.03 34.6,99.71 34.17,100.14 32.98,100.14 28.84,104.28 28.1,104.28 27.54,103.72 27.54,87.11 30.26,84.39 56.24,84.39
VDDA_GPO_B on BOTTOM: 60.11,69.79 59.98,69.92 59.98,70.45 60.06,70.53 63.74,70.53 63.8,70.47 63.8,69.84 63.74,69.79
VDDA_GPO_B on L8_PWR: 43.98,30.98 45.47,32.47 45.47,43.8 46.9,45.22 62.16,45.22 62.69,45.76 62.69,60.64 63.33,61.28 65.06,61.28 65.77,61.99 65.77,70.27 65.49,70.55 60.03,70.55 59.77,70.29 59.77,62.29 56.12,58.64 56.12,56.15 54.06,54.09 39.17,54.09 37.47,52.39 37.47,34.12 40.62,30.98
(no net) on L5_SIG: 8.57,0 0,8.57 0,130.42 8.56,138.98 89.4,138.98 89.4,125.48 91.45,125.48 91.45,0 ; 3 cut-outs
(no net) on L6_SIG: 8.57,0.01 0.01,8.57 0.01,130.42 8.57,138.98 89.4,138.98 89.4,125.48 91.42,125.48 91.42,0.04 91.4,0.01 ; 6 cut-outs
1P3_DIG_A on TOP: 42.16,76.28 44.8,76.28 44.9,76.17 44.9,74.47 44.75,74.32 42.16,74.32 42.03,74.45 42.03,76.15
1P3_DIG_A on L8_PWR: 34.01,114.07 32.33,114.07 25.97,120.43 25.18,120.43 18.47,113.73 18.47,112.97 18.49,112.95 18.49,111.11 26.5,103.1 26.5,86.14 29.8,82.84 42.58,82.84 43.14,82.28 43.14,72.73 42.83,72.43 12.15,72.43 11.87,72.71 11.87,124.02 28.05,124.02 35.47,116.6 35.47,115.53
1P3_DIG_B on TOP: 42.2,69.49 44.84,69.49 44.95,69.39 44.95,67.69 44.79,67.54 42.2,67.54 42.08,67.66 42.08,69.36
1P3_DIG_B on L8_PWR: 35.05,21.21 35.54,20.71 35.54,15.53 35.19,15.18 16.29,15.18 14.64,16.83 14.78,16.97 14.96,16.97 11.82,20.1 11.82,70.42 12.45,71.06 40.79,71.06 42.84,69.01 42.84,59.76 42.48,59.4 30.18,59.4 28.43,57.65 28.43,57.59 27.47,56.63 27.47,39.54 24.63,36.7 24.63,33.12 18.12,26.61 18.12,25.69 24.18,19.63 26.36,19.63 26.37,19.62 28.37,19.62 29.95,21.21
1P3_RF_A on TOP: 42.17,83.1 44.81,83.1 44.91,82.99 44.91,81.29 44.76,81.14 42.17,81.14 42.04,81.27 42.04,82.97
1P3_RF_A on L3_PWR: 31.45,115.58 31.45,104.25 26.02,98.82 26.02,93.61 25.99,93.59 25.99,85.38 26.86,84.52 34.98,84.52 38.34,81.17 42.58,81.17 42.78,81.37 42.78,82.51 42.77,82.52 42.77,82.85 42.76,82.87 42.76,83.43 33.73,92.46 33.73,99.77 35.64,101.69 35.64,126.4 35.63,126.42 35.63,128.19 35.09,128.74 15.22,128.74 14.74,128.26 14.74,119.57 15.15,119.16 28.07,119.16 31.48,115.76 31.48,115.58
1P3_RF_B on TOP: 42.19,62.69 44.83,62.69 44.93,62.59 44.93,60.89 44.78,60.73 42.19,60.73 42.06,60.86 42.06,62.56
1P3_RF_B on BOTTOM: 44.58,38.98 35.52,38.98 34.58,39.92 34.58,41.21 34.81,41.44 41.54,41.44 41.74,41.64 41.74,56.65 41.31,57.09 41.28,57.09 41.03,57.34 41.03,61.2 42.4,62.57 43.19,62.57 45.65,60.11 50.25,60.11 50.73,59.63 50.73,45.12
1P3_RF_B on L3_PWR: 44.74,39.61 44.48,39.87 35.34,39.87 34.91,39.43 34.91,37.27 33.94,36.31 13.83,36.31 13.65,36.13 13.65,20.46 13.67,20.43 13.67,18.88 17.53,15.02 23.4,15.02 23.48,15.1 23.48,16.7 23.38,16.8 21.72,16.8 17.71,20.82 17.71,28.74 22.21,33.24 26.14,33.24 26.18,33.2 40.51,33.2 44.74,37.43
1P8_CLK on BOTTOM: 44.84,66.37 44.84,67.91 44.91,67.98 46.06,67.98 46.74,67.3 47.53,67.3 48.06,67.83 49.66,67.83 49.84,68.01 50.53,68.01 50.63,67.91 50.68,67.91 50.68,66.38 50.55,66.26 49.16,66.26 48.86,65.96 45.25,65.96
1P8V on TOP: 54.39,64.79 53.71,64.79 53.63,64.87 53.63,65.63 53.68,65.68 54.83,65.68 54.95,65.81 54.95,67.4 55.33,67.78 55.33,68.59 54.85,69.08 54.85,69.1 54.52,69.43 54.52,71.32 54.26,71.58 53.67,71.58 53.59,71.65 53.59,72.42 53.64,72.47 54.79,72.47 54.91,72.59 54.91,74.31 55.23,74.63 55.98,74.63 56.14,74.79 56.14,78.27 56.01,78.4 53.68,78.4 53.6,78.47 53.6,79.24 53.65,79.29 54.8,79.29 54.92,79.41 54.92,81.29 55.07,81.45 55.3,81.45 55.3,92.47 55.56,92.72 66.3,92.72 66.45,92.57 66.45,89.47 65.97,88.99 61.63,88.99 61.37,89.24 61.37,90.59 61.07,90.89 58.35,90.89 57.89,90.44 57.89,86.83 58,86.73 58.94,86.73 59.06,86.6 59.06,82.18 58.71,81.83 58.71,76.29 59.19,75.81 60.74,75.81 60.92,75.63 60.92,73.06 60.74,72.89 57.23,72.89 56.47,72.12 56.47,65.39 56.41,65.33 56.41,58.67 54.39,56.65 52.26,56.65 52.26,57.65 52.33,57.72 53.42,57.72 53.5,57.8 53.5,58.76 53.58,58.84 54.95,58.84 55.15,59.04 55.15,60.77 54.63,61.29 54.63,62.97 54.64,62.98 54.64,64.54
1P8V on BOTTOM: 37.88,63.89 37.88,62.17 38.03,62.01 41.18,62.01 41.54,62.37 41.54,62.4 42.02,62.88 43.44,62.88 45.49,60.83 57.02,60.83 57.46,61.28 57.46,63.16 55.51,65.11 55.51,65.77 55.38,65.9 49.69,65.9 49.02,65.23 39.21,65.23
1P8V on L3_PWR: 34.65,50.48 31.78,50.48 31.31,50.95 31.31,54.33 32.38,55.4 41.07,55.4 41.21,55.54 41.21,61.7 41.5,61.99 41.5,63.77 41.35,63.92 37.63,63.92 35.19,61.48 24.06,61.48 22.39,59.8 22.39,51.55 27.39,46.55 32.95,46.55 33.24,46.84 33.24,49.1 33.26,49.11 33.26,49.19 33.61,49.54 34.65,49.54 34.83,49.72 34.83,50.3
3P3V on TOP: 78.54,77.03 77.96,77.61 73.41,77.61 73.19,77.84 69.32,77.84 69.22,77.74 69.22,76.47 69.35,76.34 74.76,76.34 75.52,75.58 75.52,69.2 75.67,69.05 78.21,69.05 78.54,69.38
3P3V on BOTTOM: 81.67,64.48 78.09,68.06 73.92,68.06 73.76,68.22 73.76,70.64 75.55,72.43 78.09,72.43 78.09,71.95 79.57,70.46 82.85,70.46 85,68.31 85,65.04 88.32,61.71 88.32,53.58 88.2,53.45 82.86,53.45 82.56,53.76 82.56,57.09 82.48,57.09 81.67,57.9
3P3V on L3_PWR: 47.38,58.15 80.02,58.15 81.95,60.08 83.88,60.08 84.13,59.83 84.13,52.08 83.93,51.88 38.72,51.88 38.73,51.89 37.84,51.89 36.99,51.04 31.91,51.04 31.81,51.14 31.81,53.94 32.44,54.57 43.8,54.57
3P3V on L3_PWR: 87.99,130.54 87.99,127.44 87.69,127.14 84.44,127.14 83.8,126.5 78.21,126.5 77.83,126.12 77.83,113.75 77.44,113.36 77.44,113.18 73.79,109.54 73.79,82.33 78.65,77.48 78.65,69.23 78.38,68.96 74.42,68.96 74.23,69.15 74.23,71.44 63.96,81.7 63.96,110.05 69.35,115.43 69.35,130.01 70.09,130.75 87.79,130.75
3P3V on L8_PWR: 87.99,130.54 87.99,127.44 87.69,127.14 84.44,127.14 83.8,126.5 78.21,126.5 77.83,126.12 77.83,77.48 78.65,76.67 78.65,68.8 78.54,68.69 75.88,68.69 75.56,68.38 66.68,68.38 66.68,68.39 66.39,68.68 66.39,112.65 69.35,115.61 69.35,130.01 70.09,130.75 87.79,130.75
PG_1P8V on BOTTOM: 54.43,79.48 57,79.48 57.36,79.84 57.36,86.86 58.96,88.46 69.76,88.46 70.19,88.89 70.19,91.48 69.78,91.88 54.87,91.88 54.43,91.45
PG_1P8V on L8_PWR: 54.69,70.98 54.69,64.15 53.78,63.23 53.78,60.21 54.11,59.88 56.5,59.88 59.11,62.5 59.11,71.29 56.5,73.9 56.5,82.51 56.12,82.89 44.38,82.89 43.92,82.44 43.92,72.4 44.56,71.77 53.91,71.77
TX1A_N_A on BOTTOM (solid shape): 33.17,119.28 33.17,119.27 32.96,119.06 32.76,118.5 32.97,117.93 32.82,117.78 32.82,117.78 31.94,116.9 31.93,116.9 31.15,117.18 30.35,116.96 30.21,117.1 30.21,117.12 30.28,117.19 30.28,117.19 30.97,117.71 31.69,118.19 32.95,119.45 33,119.45
TX1A_N_B on BOTTOM (solid shape): 19.37,33.77 19.94,33.57 20.5,33.78 20.65,33.63 20.66,33.63 21.53,32.75 21.53,32.74 21.26,32.02 21.41,31.26 21.24,31.09 21.24,31.09 20.72,31.79 20.24,32.5 18.98,33.76 18.98,33.81 19.15,33.98 19.16,33.98
TX1A_P_A on BOTTOM (solid shape): 32.42,120.03 32.42,119.98 31.16,118.72 30.69,118 30.17,117.31 30.17,117.3 30.1,117.23 30.07,117.23 29.93,117.37 30.15,118.17 29.87,118.96 29.87,118.97 30.75,119.84 30.75,119.84 30.91,120 31.47,119.79 32.03,119.99 32.24,120.19 32.25,120.19
TX1A_P_B on BOTTOM (solid shape): 19.71,31.97 20.43,31.5 21.12,30.98 21.13,30.98 21.15,30.95 20.99,30.79 20.22,30.96 19.48,30.68 19.47,30.68 18.59,31.56 18.59,31.57 18.43,31.72 18.65,32.28 18.44,32.85 18.24,33.05 18.24,33.06 18.41,33.23 18.45,33.23
TX2A_N_A on BOTTOM (solid shape): 19.87,108.96 20.65,108.68 21.46,108.9 21.6,108.76 21.6,108.73 21.52,108.66 21.52,108.66 20.83,108.14 20.11,107.67 18.85,106.41 18.8,106.41 18.64,106.58 18.64,106.59 18.84,106.79 19.04,107.36 18.83,107.92 18.98,108.07 18.98,108.08 19.86,108.96
TX2A_N_B on BOTTOM (solid shape): 29.77,22.34 29.77,22.33 30.29,21.64 30.77,20.92 32.02,19.66 32.02,19.61 31.86,19.45 31.84,19.45 31.64,19.65 31.07,19.85 30.51,19.64 30.36,19.8 30.35,19.8 29.47,20.67 29.47,20.68 29.75,21.47 29.53,22.27 29.67,22.41 29.7,22.41
TX2A_P_A on BOTTOM (solid shape): 21.87,108.48 21.65,107.68 21.93,106.9 21.93,106.89 21.05,106.01 21.05,106.01 20.9,105.86 20.33,106.07 19.77,105.87 19.56,105.66 19.55,105.66 19.38,105.83 19.38,105.88 20.64,107.14 21.12,107.85 21.63,108.55 21.63,108.55 21.71,108.62 21.73,108.62
TX2A_P_B on BOTTOM (solid shape): 32.42,21.86 32.42,21.86 32.57,21.71 32.36,21.15 32.56,20.58 32.77,20.37 32.77,20.36 32.6,20.19 32.55,20.19 31.3,21.45 30.58,21.93 29.89,22.45 29.88,22.45 29.81,22.52 29.81,22.54 29.95,22.68 30.75,22.46 31.53,22.74 31.54,22.74
UNNAMED_2_CAP_I230_N1 on BOTTOM (solid shape): 21.86,122.12 21.71,121.59 21.87,121.08 22.11,120.84 22.11,120.82 21.88,120.59 21.85,120.59 21.61,120.83 21.37,121.11 21.15,121.42 20.91,121.66 20.91,121.69 21.17,121.95 21.17,121.95 21.59,122.37 21.61,122.37
UNNAMED_2_CAP_I231_N1 on BOTTOM (solid shape): 20.59,120.86 20.89,120.64 21.18,120.4 21.42,120.16 21.42,120.13 21.19,119.9 21.17,119.9 20.93,120.14 20.41,120.3 19.89,120.15 19.64,120.4 19.64,120.42 20.06,120.84 20.06,120.84 20.32,121.1 20.35,121.1
UNNAMED_2_CAP_I232_N1 on BOTTOM (solid shape): 19.24,119.5 19.1,118.98 19.25,118.46 19.49,118.23 19.49,118.2 19.26,117.97 19.24,117.97 19,118.21 18.76,118.5 18.54,118.81 18.29,119.05 18.29,119.07 18.56,119.33 18.56,119.34 18.97,119.75 18.99,119.75
UNNAMED_2_CAP_I233_N1 on BOTTOM (solid shape): 17.97,118.24 18.28,118.02 18.57,117.78 18.81,117.54 18.81,117.52 18.58,117.29 18.55,117.29 18.32,117.52 17.8,117.68 17.28,117.54 17.03,117.79 17.03,117.81 17.44,118.22 17.45,118.22 17.71,118.48 17.73,118.48
UNNAMED_4_ADM7150_I1046_REF on TOP: 62.7,54.41 62.63,54.49 62.63,56.43 62.62,56.44 62.62,56.47 65.19,56.47 65.54,56.12 65.54,54.47 65.48,54.41
UNNAMED_4_ADM7150_I1046_VIN on TOP: 61.32,64.07 61.91,63.49 63.79,63.49 64.6,62.67 67.62,62.67 67.81,62.49 67.81,57.82 67.02,57.03 62.68,57.03 62.6,57.11 62.6,59.14 62.36,59.37 59.6,59.37 59.22,59.75 59.22,64.02 59.27,64.07
UNNAMED_4_ADM7150_I1046_VIN on TOP: 64.47,67.53 64.35,67.4 62.39,67.4 62.24,67.25 62.24,66.74 62.06,66.56 60.1,66.56 60.03,66.64 60.03,69.05 60.03,69.05 60.03,70.79 60.26,71.03 64.3,71.03 64.47,70.86
UNNAMED_4_ADM7150_I1046_VREG on TOP: 56.98,61.86 58.88,61.86 58.91,61.84 58.91,58.36 58.86,58.31 56.98,58.31 56.97,58.32 56.89,58.32 56.78,58.43 56.78,61.81 56.83,61.86 56.88,61.86 56.9,61.84 56.95,61.89
UNNAMED_4_ADM7150_I1142_REF on TOP: 61.53,72.4 61.53,71.62 61.55,71.59 64.4,71.59 64.47,71.67 64.47,74 64.42,74.05 62.87,74.05 62.77,73.95 62.77,72.53 62.72,72.48 61.6,72.48
UNNAMED_4_ADM7150_I1142_VREG on TOP: 68.18,69.89 72.4,69.89 72.45,69.84 72.45,67.93 72.4,67.88 69.32,67.88 68.11,69.1 68.11,69.81
UNNAMED_4_ADP1755_I730_VOUT1 on TOP: 45.42,79.41 48.06,79.41 48.17,79.31 48.27,79.31 48.34,79.39 48.34,81.62 48.39,81.67 49.18,81.67 49.39,81.47 49.39,79.46 49.51,79.34 50.55,79.34 50.63,79.26 50.63,78.24 50.58,78.19 50.12,78.19 50.05,78.12 50.05,77.28 49.97,77.2 42.3,77.2 42.15,77.36 42.15,80.45 42.27,80.58 45.27,80.58 45.35,80.51 45.35,79.49
UNNAMED_4_ADP1755_I776_VOUT1 on TOP: 45.41,72.59 48.05,72.59 48.16,72.49 48.26,72.49 48.33,72.57 48.33,74.8 48.38,74.85 49.17,74.85 49.38,74.65 49.38,72.64 49.5,72.52 50.54,72.52 50.62,72.44 50.62,71.42 50.57,71.37 50.11,71.37 50.04,71.3 50.04,70.46 49.96,70.38 42.64,70.38 42.57,70.46 42.57,73.63 42.69,73.76 45.26,73.76 45.34,73.69 45.34,72.67
UNNAMED_4_ADP1755_I987_VOUT1 on TOP: 45.44,59.01 48.08,59.01 48.18,58.91 48.28,58.91 48.36,58.98 48.36,61.22 48.41,61.27 49.2,61.27 49.4,61.06 49.4,59.06 49.53,58.93 50.57,58.93 50.65,58.85 50.65,57.84 50.59,57.79 50.14,57.79 50.06,57.71 50.06,56.87 49.98,56.8 42.67,56.8 42.59,56.87 42.59,60.05 42.72,60.18 45.29,60.18 45.36,60.1 45.36,59.08
UNNAMED_4_ADP1755_I997_VOUT1 on TOP: 45.45,65.81 48.09,65.81 48.2,65.71 48.3,65.71 48.37,65.78 48.37,68.02 48.43,68.07 49.21,68.07 49.42,67.87 49.42,65.86 49.54,65.73 50.58,65.73 50.66,65.66 50.66,64.64 50.61,64.59 50.15,64.59 50.08,64.51 50.08,63.68 50,63.6 42.68,63.6 42.61,63.68 42.61,66.85 42.74,66.98 45.3,66.98 45.38,66.9 45.38,65.89
UNNAMED_4_ADP2164_I831_PVIN1 on TOP: 72.14,78.68 71.99,78.52 69.3,78.52 69.2,78.63 69.2,80.35 68.99,80.56 68.21,80.56 68.16,80.61 68.16,81.8 68.28,81.93 69.32,81.93 69.58,82.18 69.58,82.33 70.01,82.77 70.01,85.18 70.19,85.36 70.39,85.36 70.39,86.07 70.44,86.12 71.66,86.12 71.76,86.02 71.76,85.33 71.51,85.08 71.51,80.73 71.58,80.66 71.97,80.66 72.14,80.48
UNNAMED_4_ADP2164_I831_PVIN1 on BOTTOM: 64.19,74.23 64.19,69.1 63.79,68.69 63.79,63.41 64.07,63.13 71.23,63.13 71.66,63.56 71.66,65.09 71.64,65.09 71.64,84.06 71.53,84.16 70.34,84.16 70.21,84.04 70.21,82.28 69.78,81.85 65.59,81.85 64.21,80.47 64.21,74.24
UNNAMED_4_ADP2164_I831_SW1 on TOP: 68.36,76.18 66.65,76.18 66.58,76.25 66.58,80.21 66.78,80.21 67,80.43 67,80.53 67.08,80.61 67.38,80.61 67.38,80.61 67.88,80.11 68.44,80.11 68.5,80.06 68.5,80.03 68.5,76.33
UNNAMED_4_ADP2164_I831_SYNC on BOTTOM: 64.17,87.64 64.17,82.56 64.35,82.38 69.32,82.38 69.34,82.4 69.67,82.4 69.78,82.51 69.78,84.49 69.76,84.49 69.63,84.37 69.63,84.65 69.73,84.75 71.94,84.75 72.42,84.26 74.35,84.26 74.51,84.42 74.51,87.64 74.3,87.85 64.37,87.85
UNNAMED_4_CAP_I833_N2 on TOP: 66.05,79.95 65.89,80.11 64.51,80.11 64.04,79.63 61.6,79.63 61.28,79.96 59.35,79.96 59.24,79.84 59.24,76.47 59.34,76.37 61.42,76.37 61.78,76.01 65.84,76.01 66.05,76.21
UNNAMED_4_FERRITE_I816_N2 on BOTTOM: 52.07,72.96 52.07,71.06 52.01,71 50.4,71 50.34,71.06 50.34,72.94 52.04,72.94
UNNAMED_9_CAP_I165_N1 on BOTTOM (solid shape): 21.14,19.39 21.14,19.36 20.91,19.13 20.75,18.61 20.89,18.09 20.64,17.84 20.62,17.84 20.21,18.25 20.21,18.26 19.95,18.52 19.95,18.54 20.19,18.79 20.41,19.09 20.65,19.38 20.89,19.62 20.91,19.62
UNNAMED_9_CAP_I167_N1 on BOTTOM (solid shape): 20.46,20.07 20.46,20.05 20.22,19.81 19.93,19.57 19.63,19.35 19.38,19.11 19.36,19.11 19.1,19.37 19.09,19.37 18.68,19.78 18.68,19.8 18.93,20.05 19.45,19.91 19.97,20.07 20.2,20.3 20.23,20.3
UNNAMED_9_CAP_I168_N1 on BOTTOM (solid shape): 18.53,22.01 18.53,21.98 18.29,21.74 18.13,21.23 18.28,20.7 18.03,20.46 18.01,20.46 17.59,20.87 17.59,20.87 17.33,21.13 17.33,21.16 17.58,21.4 17.79,21.71 18.04,21.99 18.27,22.23 18.3,22.23
UNNAMED_9_CAP_I170_N1 on BOTTOM (solid shape): 17.84,22.69 17.84,22.66 17.61,22.42 17.32,22.18 17.01,21.96 16.77,21.72 16.74,21.72 16.48,21.98 16.48,21.98 16.07,22.4 16.07,22.42 16.31,22.67 16.84,22.52 17.35,22.68 17.59,22.92 17.62,22.92
